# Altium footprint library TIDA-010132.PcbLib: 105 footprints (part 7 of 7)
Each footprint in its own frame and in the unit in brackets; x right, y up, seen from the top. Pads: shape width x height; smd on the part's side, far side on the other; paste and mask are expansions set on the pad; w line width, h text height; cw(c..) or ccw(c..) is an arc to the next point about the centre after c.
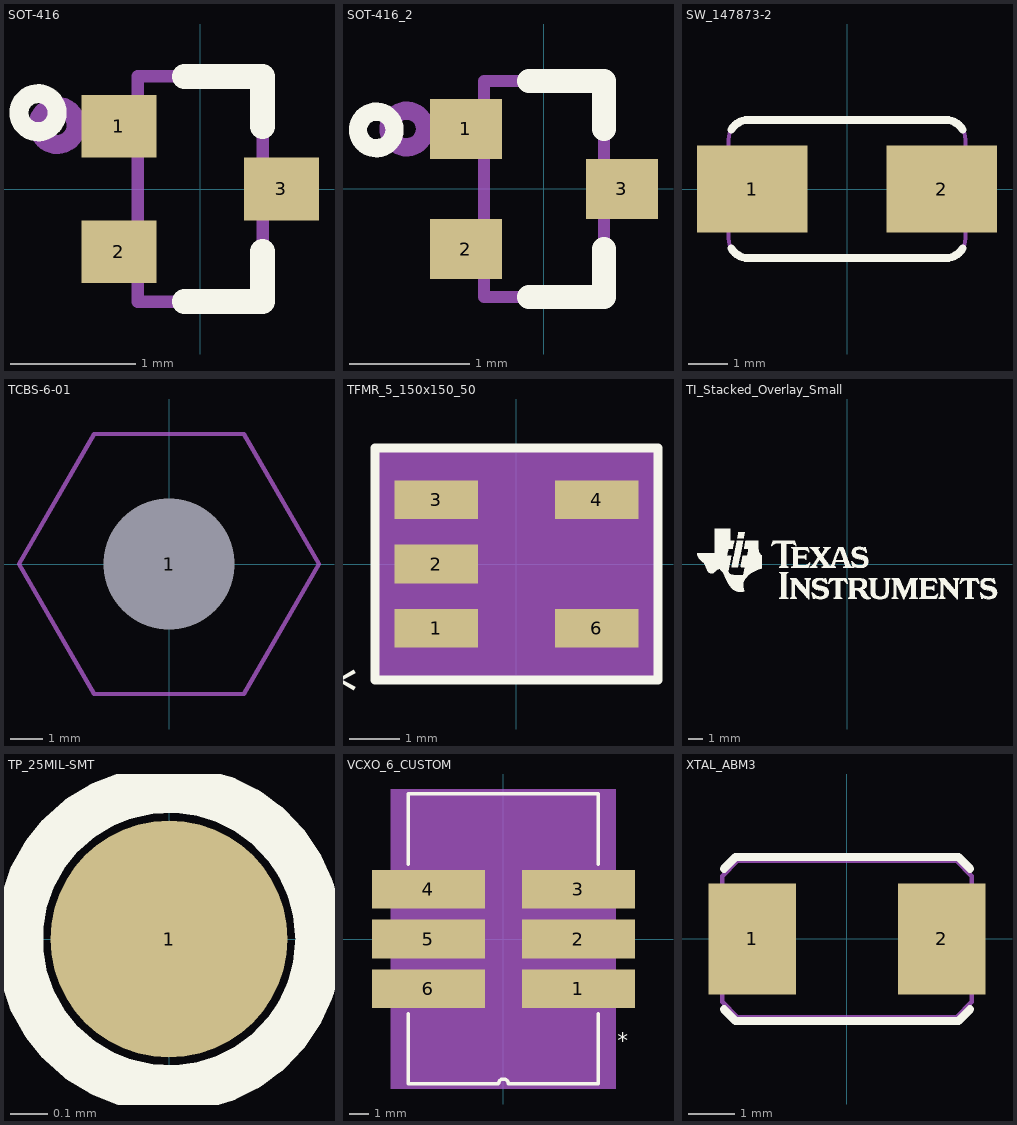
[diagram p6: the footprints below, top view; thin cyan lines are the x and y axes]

## SOT-416 [mm] "NXP recommended footprint."
height 0.95
pads (3):
  rect 0.6x0.5 smd: 1(-0.65,0.5) 2(-0.65,-0.5) 3(0.65,0)
Top Overlay:
  circle w0.152: c-1.295,0.61 r0.152
  lines w0.2: -0.125,-0.9 0.359,-0.9 0.5,-0.9 0.5,-0.5 ; -0.125,0.9 0.359,0.9 0.5,0.9 0.5,0.5
Mechanical 5:
  circle w0.152: c-1.143,0.508 r0.152
  lines w0.1: -0.551,-0.6 -0.6,-0.6 -0.65,-0.6 -0.8,-0.6 -0.8,-0.4 -0.65,-0.4 -0.6,-0.4 -0.551,-0.4 ; -0.551,0.4 -0.6,0.4 -0.65,0.4 -0.8,0.4 -0.8,0.6 -0.65,0.6 -0.6,0.6 -0.551,0.6 ; -0.5,-0.6 -0.5,-0.9 -0.359,-0.9 0.359,-0.9 0.5,-0.9 0.5,-0.1 ; -0.5,-0.4 -0.5,0.4 ; -0.5,0.6 -0.5,0.9 -0.359,0.9 0.359,0.9 0.5,0.9 0.5,0.1 ; 0.551,-0.1 0.6,-0.1 0.65,-0.1 0.8,-0.1 0.8,0.1 0.65,0.1 0.6,0.1 0.551,0.1
  text ".Designator" at -0.175,0.725 h0.46
3D body "SOT-416.stp": height 0.82, standoff 0.02, extent -0.8,-0.9 0.8,0.9

## SOT-416_2 [mm]
pads (3):
  rect 0.6x0.5 smd: 1(-0.65,0.5) 2(-0.65,-0.5) 3(0.65,0)
Top Overlay:
  circle w0.152: c-1.397,0.492 r0.152
  lines w0.2: -0.125,-0.9 0.359,-0.9 0.5,-0.9 0.5,-0.5 ; -0.125,0.9 0.359,0.9 0.5,0.9 0.5,0.5
Mechanical 5:
  circle w0.152: c-1.143,0.5 r0.152
  lines w0.1: -0.551,-0.6 -0.6,-0.6 -0.65,-0.6 -0.8,-0.6 -0.8,-0.4 -0.65,-0.4 -0.6,-0.4 -0.551,-0.4 ; -0.551,0.4 -0.6,0.4 -0.65,0.4 -0.8,0.4 -0.8,0.6 -0.65,0.6 -0.6,0.6 -0.551,0.6 ; -0.5,-0.6 -0.5,-0.9 -0.359,-0.9 0.359,-0.9 0.5,-0.9 0.5,-0.1 ; -0.5,-0.4 -0.5,0.4 ; -0.5,0.6 -0.5,0.9 -0.359,0.9 0.359,0.9 0.5,0.9 0.5,0.1 ; 0.551,-0.1 0.6,-0.1 0.65,-0.1 0.8,-0.1 0.8,0.1 0.65,0.1 0.6,0.1 0.551,0.1
  text ".Designator" at -0.175,0.725 h0.46
3D body "SOT-416.stp": height 0.82, standoff 0.02, extent -0.8,-0.9 0.8,0.9

## SW_147873-2 [mm] "SMD, 2-Leads, Body 6x3.5mm"
height 4.65
pads (2):
  rect 2.8x2.2 smd: 1(-2.4,0) 2(2.4,0)
Top Overlay:
  lines w0.2: -2.933,-1.5 ccw(c-2.5,-1.25) -2.5,-1.75 2.5,-1.75 ccw(c2.5,-1.25) 2.933,-1.5 ; -2.933,1.5 cw(c-2.5,1.25) -2.5,1.75 2.5,1.75 cw(c2.5,1.25) 2.933,1.5
Mechanical 5:
  lines w0.1: -3,-0.5 -3.1,-0.5 -3.4,-0.5 -3.4,0.5 -3.1,0.5 -3,0.5 ; 3,-0.5 3.1,-0.5 3.4,-0.5 3.4,0.5 3.1,0.5 3,0.5 ; -3,-1.25 ccw(c-2.5,-1.25) -2.5,-1.75 2.5,-1.75 ccw(c2.5,-1.25) 3,-1.25 3,-1.125 3,1.125 3,1.25 ccw(c2.5,1.25) 2.5,1.75 -2.5,1.75 ccw(c-2.5,1.25) -3,1.25 -3,1.125 -3,-1.125 -3,-1.25
  text ".Designator" at -1.524,-0.508 h0.46
3D body "c-147873-2-k-3d.stp": height 4.5, standoff 0, extent -3.4,-1.75 3.4,1.75

## TCBS-6-01 [mil] "Richco Plastics"
height 375
pads (1):
  round 60 hole 157 unplated: 1(0,0)
Mechanical 5:
  lines w5: -179.57,0 -89.79,155.51 89.78,155.51 179.56,0 89.78,-155.51 -89.79,-155.51 -179.57,0
  text ".Designator" at -60,-20 h18
3D body "Richco_TCBS-6.stp": height 374.61, standoff -387.57, extent -179.57,-155.51 179.56,155.52

## TFMR_5_150x150_50 [mil] "TFMR_5_150X150_50"
height 375.2
pads (5):
  rect 65x30 smd: 1(-62.5,-50) 2(-62.5,0) 3(-62.5,50) 4(62.5,50) 6(62.5,-50)
Top Overlay:
  lines w7: -110,-90 110,-90 110,90 -110,90 -110,-90
  text "*" at -123.2,-61 h42
Mechanical 5:
  lines w1: -75,-75 75,-75 75,75 -75,75 -75,-75
  text "*" at -80,-48.33 h18
Mechanical 16:
  region: 110,-90 -110,-90 -110,90 110,90
Mechanical 27:
  text "2" at -52.5,0 h25
  text "4" at 72.5,50 h25
  text "6" at 72.5,-50 h25
  text "1" at -52.5,-50 h25
  text "3" at -52.5,50 h25

## TI_Stacked_Overlay_Small [mil]
Top Overlay:
  drawing of 18 lines, arcs and shapes, not listed

## TP_25MIL-SMT [mil]
height 337.8
pads (1):
  round 25 smd mask-2.5: 1(0,0)
Top Overlay:
  circle w5: c0,0 r15.81
Mechanical 5:
  text ".Designator" at 0,0 h18

## VCXO_6_CUSTOM [mil] "VCXO_6_CUSTOM"
pads (6):
  rect 226.01x77 smd: 1(150.01,-100) 2(150.01,0) 3(150.01,100) 4(-150.01,100) 5(-150.01,0) 6(-150.01,-100)
Top Overlay:
  lines w7: -190.01,-150 -190,-290 -10.01,-290 cw(c-0.01,-289.99) 10,-290 190,-290 189.99,-150 ; -190.01,150 -190.01,290.01 189.99,290.01 189.99,150
  text "*" at 250,-175 h31.1
  text ".Designator" at 257.9,-221.08 h31.1
Mechanical 16:
  circle w1: c125,-224.99 r25
  region: 224.99,300 -225.01,300 -225,-300 224.99,-300
  lines w1: -15,0 14.99,0 ; -0.01,-15 -0.01,15 ; -172,-275.5 -172.01,275.5 172,275.5 172,-275.5 -172,-275.5 ; -107.01,-138.5 -107.01,-61.5 -37,-61.5 -37,-138.5 -107.01,-138.5 ; -107.01,-38.5 -107.01,38.5 -37,38.5 -37,-38.5 -107.01,-38.5 ; -107.01,61.5 -107.01,138.5 -37,138.5 -37,61.5 -107.01,61.5 ; -103,-150.49 -103.01,150.5 103,150.5 103,-150.5 -103,-150.49 ; 34.99,-99.99 84.99,-75 84.99,-125 34.99,-99.99 ; 37,-138.49 37,-61.5 106.99,-61.5 106.99,-138.5 37,-138.49 ; 37,-38.49 36.99,38.5 106.99,38.5 106.99,-38.5 37,-38.49 ; 37,61.5 36.99,138.5 106.99,138.5 106.99,61.5 37,61.5
Mechanical 22:
  text "1" at 142.92,-107.07 h25
  text "3" at 142.92,92.93 h25
  text "2" at 142.92,-7.07 h25
  text "5" at -157.08,-7.07 h25
  text "4" at -157.08,92.93 h25
  text "6" at -157.08,-107.07 h25
3D body: height 150, standoff 0, extent -225.01,-300 224.99,300

## XTAL_ABM3 [mm] "Abracon recommended land pattern 12.28.10"
height 1.3
pads (2):
  rect 1.9x2.4 smd: 1(-2.05,0) 2(2.05,0)
Top Overlay:
  lines w0.178: -2.667,-1.524 -2.413,-1.778 0,-1.778 2.413,-1.778 2.667,-1.524 ; -2.667,1.524 -2.413,1.778 0,1.778 2.413,1.778 2.667,1.524
Mechanical 5:
  lines w0.1: -2.7,-1.364 -2.7,1.364 -2.364,1.7 2.364,1.7 2.7,1.364 2.7,-1.364 2.364,-1.7 -2.364,-1.7 -2.7,-1.364
  text ".Designator" at -1.778,-0.508 h0.46
3D body "Abracon_ABM3.stp": height 1.3, standoff 0, extent -2.597,-1.698 2.603,1.702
